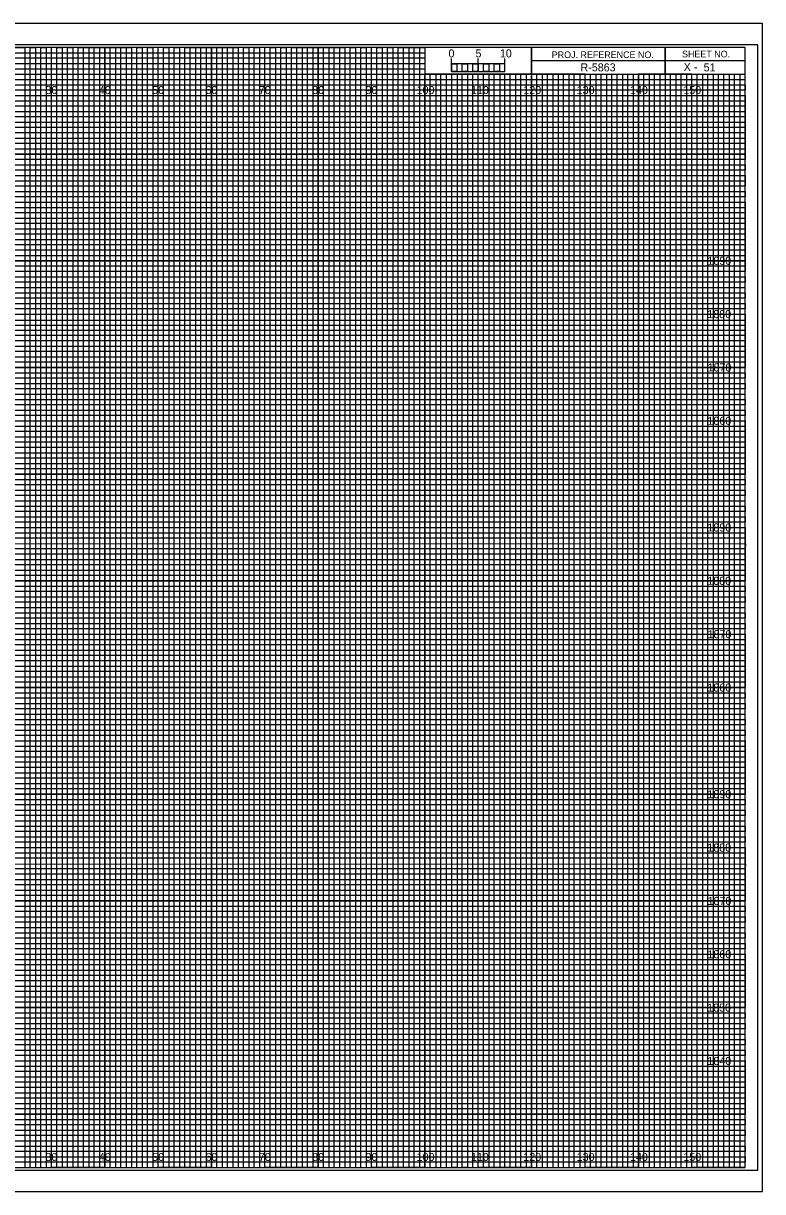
# Model space of a CAD drawing. Extents: x -13 to 323, y 216 to 434.
# Drawn here: x 184.7 to 323.3, y 215.5 to 434.5 of the extents above; entities that cross this region are included whole.
import ezdxf

# ---------------------------------------------------------------- set-up
doc = ezdxf.new("R2010")
doc.units = 0
for name, color, linetype in [('Prop XS Bar Scale Labels', 7, 'Continuous'), ('Prop XS Elevation Labels', 7, 'Continuous'), ('Prop XS Offset Labels', 7, 'Continuous'), ('Prop XS Project Number', 7, 'Continuous'), ('Prop XS Sheet Number', 7, 'Continuous'), ('Sheet Cross Section CELL', 7, 'Continuous'), ('Sheet Cross Section Grid Major CELL', 7, 'Continuous'), ('Sheet Cross Section Grid Middle CELL', 7, 'Continuous'), ('Sheet Cross Section Grid Minor 1 CELL', 7, 'Continuous'), ('Sheet Cross Section Grid Minor 2 CELL', 7, 'Continuous'), ('Sheet Cross Section Scale CELL', 7, 'Continuous'), ('Sheet Cutting Line CELL', 7, 'Continuous'), ('Sheet DOT Grid CELL', 7, 'Continuous'), ('Sheet Plot Border Inside CELL', 7, 'Continuous'), ('Sheet Plot Border Outside CELL', 7, 'Continuous')]:
    doc.layers.add(name, color=color, linetype=linetype)

msp = doc.modelspace()

# ---------------------------------------------------------------- linework, layer by layer
at = {"layer": 'Sheet Cross Section CELL'}
for p, q in [((305, 430), (305, 425)), ((305, 425), (305, 430)), ((280, 427.5), (280, 425)), ((320, 427.49), (280, 427.49)), ((280, 425), (320, 425))]:
    msp.add_line(p, q, dxfattribs=at)
for points in [[(320, 430), (0, 430), (0, 220), (320, 220)], [(280, 430), (260, 430), (260, 425.03), (280, 425.03)], [(320, 430), (280, 430), (280, 425), (320, 425)]]:
    msp.add_lwpolyline(points, close=True, dxfattribs=at)
at = {"layer": 'Sheet Cross Section Grid Major CELL'}
for p, q in [((190, 430), (180, 430)), ((190, 220), (190, 430)), ((210, 430), (200, 430)), ((200, 430), (200, 220)), ((210, 220), (210, 430)), ((230, 430), (220, 430)), ((220, 430), (220, 220)), ((230, 220), (230, 430)), ((250, 430), (240, 430)), ((240, 430), (240, 220)), ((250, 220), (250, 430)), ((260, 430), (260, 220)), ((270, 220), (270, 425)), ((290, 425), (280, 425)), ((280, 425), (280, 220)), ((290, 220), (290, 425)), ((310, 425), (300, 425)), ((300, 425), (300, 220)), ((310, 220), (310, 425)), ((200, 220), (190, 220)), ((220, 220), (210, 220)), ((240, 220), (230, 220)), ((260, 220), (250, 220)), ((280, 220), (270, 220)), ((300, 220), (290, 220)), ((320, 220), (310, 220)), ((320, 220), (320, 220))]:
    msp.add_line(p, q, dxfattribs=at)
for points in [[(0, 420), (320, 420), (320, 410), (0, 410)], [(0, 400), (320, 400), (320, 390), (0, 390)], [(0, 380), (320, 380), (320, 370), (0, 370)], [(0, 360), (320, 360), (320, 350), (0, 350)], [(0, 340), (320, 340), (320, 330), (0, 330)], [(0, 320), (320, 320), (320, 310), (0, 310)], [(0, 300), (320, 300), (320, 290), (0, 290)], [(0, 280), (320, 280), (320, 270), (0, 270)], [(0, 260), (320, 260), (320, 250), (0, 250)], [(0, 240), (320, 240), (320, 230), (0, 230)]]:
    msp.add_lwpolyline(points, dxfattribs=at)
at = {"layer": 'Sheet Cross Section Grid Middle CELL'}
for points in [[(175, 430), (185, 430), (185, 220), (195, 220), (195, 430), (205, 430), (205, 220), (215, 220), (215, 430), (225, 430), (225, 220), (235, 220), (235, 430), (245, 430), (245, 220), (255, 220), (255, 430), (259.93, 430), (260, 430), (260, 425), (264.99, 425), (264.99, 220), (275, 220), (275, 425), (285, 425), (285, 220), (295, 220), (295, 425), (305, 425), (305, 220), (315, 220), (315, 425)], [(0, 425), (275, 425)], [(0, 405), (320, 405), (320, 415), (0, 415)], [(0, 385), (320, 385), (320, 395), (0, 395)], [(0, 365), (320, 365), (320, 375), (0, 375)], [(0, 345), (320, 345), (320, 355), (0, 355)], [(0, 325), (320, 325), (320, 335), (0, 335)], [(0, 305), (320, 305), (320, 315), (0, 315)], [(0, 285), (320, 285), (320, 295), (0, 295)], [(0, 265), (320, 265), (320, 275), (0, 275)], [(0, 245), (320, 245), (320, 255), (0, 255)], [(0, 225), (320, 225), (320, 235), (0, 235)]]:
    msp.add_lwpolyline(points, dxfattribs=at)
at = {"layer": 'Sheet Cross Section Grid Minor 1 CELL'}
for p, q in [((0, 429), (260, 429)), ((260, 427.98), (0, 427.98)), ((260, 429), (260, 427.98)), ((0, 427), (260, 427)), ((260, 425.89), (0, 425.89)), ((260, 427), (260, 425.89)), ((0, 424), (320, 424))]:
    msp.add_line(p, q, dxfattribs=at)
for points in [[(0, 423), (270, 423), (320, 423), (320, 422), (0, 422)], [(0, 421), (320, 421), (320, 419), (0, 419)], [(0, 418), (320, 418), (320, 417), (0, 416.98)], [(0, 416), (320, 416), (320, 414), (0, 414)], [(0, 413), (320, 413), (320, 412), (0, 412)], [(0, 411), (320, 411), (320, 409), (0, 409)], [(0, 408), (320, 408), (320, 407), (0, 407)], [(0, 406), (320, 406), (320, 404), (0, 404)], [(0, 403), (320, 403), (320, 402), (0, 402)], [(0, 401), (320, 401), (320, 399), (0, 399)], [(0, 398), (320, 398), (320, 397), (0, 397)], [(0, 396), (320, 396), (320, 393.95), (320, 393), (320, 392), (0, 392)], [(0, 394), (320, 394), (320, 393), (0, 393)], [(0, 391), (320, 391), (320, 389), (0, 389.03)], [(0, 389.03), (320, 389), (320, 388), (0, 388)], [(0, 387), (320, 387), (320, 386), (0, 386)], [(0, 384), (320, 384), (320, 383), (0, 383)], [(0, 382), (320, 382), (320, 381), (0, 381)], [(-0.07, 378.89), (320, 378.89), (320, 377.88), (-0.07, 377.88)], [(0, 377), (320, 377), (320, 376), (0, 376)], [(0, 374), (320, 374), (320, 373), (0, 373)], [(0, 372), (320, 372), (320, 371), (0, 371)], [(0, 369), (320, 369), (320, 368), (0, 368)], [(0, 367), (320, 367), (320, 366), (0, 366)], [(0, 364), (320, 364), (320, 363), (0, 363)], [(0, 362), (320, 362), (320, 361), (0, 361)], [(0, 359), (320, 359), (319.99, 357.98), (0, 358)], [(0, 357), (320, 357), (320, 356), (0, 356)], [(0, 354), (320, 354), (320, 353), (0, 353)], [(0, 352), (320, 352), (320, 351), (0, 351)], [(0, 349), (320, 349), (320, 348), (0, 348)], [(0, 347), (320, 347), (320, 346), (0, 346)], [(0, 344), (320, 344), (320, 343), (0, 343)], [(0, 342), (320, 342), (320, 341), (0, 341)], [(0, 339), (320, 339), (320, 338), (0, 338)], [(0, 336.99), (320.07, 336.91), (320, 336), (0, 336)], [(0, 334), (320, 334), (320, 333), (0, 333)], [(0, 332), (320, 332), (320, 331), (0, 331)], [(0, 329), (320, 329), (320, 328), (0, 328)], [(0, 327), (320, 327), (320, 326), (0, 326)], [(0, 324), (320, 324), (320, 323), (0, 323)], [(0, 322), (320, 322), (320, 321), (0, 321)], [(0, 319), (320, 319), (320, 318), (0, 318)], [(0, 317), (320, 317), (320, 316), (0, 316)], [(0, 314), (320, 314), (320, 313), (0, 313)], [(0, 312), (320, 312), (320, 311), (0, 311)], [(0, 309), (320, 309), (320, 308), (0, 308)], [(0, 307), (320, 307), (320, 306), (0, 306)], [(0, 304), (320, 304), (320, 303), (0, 303)], [(0, 302), (320, 302), (320, 301), (0, 301)], [(0, 299), (320, 299), (319.99, 297.98), (0, 298)], [(0, 297), (320, 297), (320, 296), (0, 296)], [(0, 294), (320, 294), (320, 293), (0, 293)], [(0, 292), (320, 292), (320, 291), (0, 291)], [(0, 289), (320, 289), (320, 288), (0, 288)], [(0, 287), (320, 287), (320, 286), (0, 286)], [(0, 284), (320, 284), (320, 283), (0, 283)], [(0, 282), (320, 282), (320, 281), (0, 281)], [(0, 279), (320, 279), (320, 278), (0, 278)], [(0, 276.99), (320.07, 276.91), (320, 276), (0, 276)], [(0, 274), (320, 274), (320, 273), (0, 273)], [(0, 272), (320, 272), (320, 271), (0, 271)], [(0, 269), (320, 269), (320, 268), (0, 268)], [(0, 267), (320, 267), (320, 266), (0, 266)], [(0, 264), (320, 264), (320, 263), (0, 263)], [(0, 262), (320, 262), (320, 261), (0, 261)], [(0, 259), (320, 259), (320, 258), (0, 258)], [(0, 257), (320, 257), (320, 256), (0, 256)], [(0, 254), (320, 254), (320, 253), (0, 253)], [(0, 252), (320, 252), (320, 251), (0, 251)], [(0, 249), (320, 249), (320, 248), (0, 248)], [(0, 247), (320, 247), (320, 246), (0, 246)], [(0, 244), (320, 244), (320, 243), (0, 243)], [(0, 242), (320, 242), (320, 241), (0, 241)], [(0, 239), (320, 239), (320, 238), (0, 238)], [(0, 237), (320, 237), (320, 236), (0, 236)], [(0, 234), (320, 234), (320, 233), (0, 233)], [(0, 232), (320, 232), (320, 231), (0, 231)], [(0, 229), (320, 229), (320, 228), (0, 228)], [(0, 227), (320, 227), (320, 226), (0, 226)], [(0, 224), (320, 224), (320, 223), (0, 223)], [(0, 222), (320, 222), (320, 221), (0, 221)]]:
    msp.add_lwpolyline(points, dxfattribs=at)
at = {"layer": 'Sheet Cross Section Grid Minor 2 CELL'}
for p, q in [((267, 425), (266.01, 425)), ((266.01, 425), (266.01, 220)), ((267, 220), (267, 425)), ((269, 425), (268, 425)), ((268, 425), (268, 220)), ((269, 220), (269, 425)), ((266.01, 220), (265, 220)), ((268, 220), (267, 220))]:
    msp.add_line(p, q, dxfattribs=at)
for points in [[(185, 220), (186, 220), (186, 430), (187, 430), (187, 220)], [(187, 220), (188, 220), (188, 430), (189, 430), (189, 220)], [(190, 220), (191, 220), (191, 430), (192, 430), (192, 220)], [(192, 220), (193, 220), (193, 430), (194, 430), (194, 220)], [(195, 220), (196, 220), (196, 430), (197, 430), (197, 220)], [(197, 220), (198, 220), (198, 430), (199, 430), (199, 220)], [(200, 220), (201, 220), (201, 430), (202, 430), (202, 220)], [(202, 220), (203, 220), (203, 430), (204, 430), (204, 220)], [(205, 220), (206, 220), (206, 430), (207, 430), (207, 220)], [(207, 220), (208, 220), (208, 430), (209, 430), (209, 220)], [(210, 220), (211, 220), (211, 430), (212, 430), (212, 220)], [(212, 220), (213, 220), (213, 430), (214, 430), (214, 220)], [(215, 220), (216, 220), (216, 430), (217, 430), (217, 220)], [(217, 220), (218, 220), (218, 430), (219, 430), (219, 220)], [(220, 220), (221, 220), (221, 430), (222, 430), (222, 220)], [(222, 220), (223, 220), (223, 430), (224, 430), (224, 220)], [(225, 220), (226, 220), (226, 430), (227, 430), (227, 220)], [(227, 220), (228, 220), (228, 430), (229, 430), (229, 220)], [(230, 220), (231, 220), (231, 430), (232, 430), (232, 220)], [(232, 220), (233, 220), (233, 430), (234, 430), (234, 220)], [(235, 220), (236, 220), (236, 430), (237, 430), (237, 220)], [(237, 220), (238, 220), (238, 430), (239, 430), (239, 220)], [(240, 220), (241, 220), (241, 430), (242, 430), (242, 220)], [(242, 220), (243, 220), (243, 430), (244, 430), (244, 220)], [(245, 220), (246, 220), (246, 430), (247, 430), (247, 220)], [(247, 220), (248, 220), (248, 430), (249, 430), (249, 220)], [(250, 220), (251, 220), (251, 430), (252, 430), (252, 220)], [(252, 220), (253, 220), (253, 430), (254, 430), (254, 220)], [(255, 220), (256, 220), (256, 430), (257, 430), (257, 220)], [(257, 220), (258, 220), (258, 430), (259, 430), (259, 220)], [(260, 220), (261, 220), (261, 425), (262.02, 425), (262.02, 220)], [(262, 220), (263, 220), (263, 425), (263.99, 425), (263.99, 220)], [(270, 220), (270.98, 220), (270.98, 425), (272, 425), (272, 220)], [(272, 220), (273, 220), (273, 425), (274.05, 425), (274.05, 220)], [(275, 220), (276, 220), (276, 425), (277, 425), (277, 220)], [(277, 220), (278, 220), (278, 425), (279, 425), (279, 220)], [(280, 220), (281, 220), (281, 425), (282, 425), (282, 220)], [(282, 220), (283, 220), (283, 425), (284, 425), (284, 220)], [(285, 220), (286, 220), (286, 425), (287, 425), (287, 220)], [(287, 220), (288, 220), (288, 425), (289, 425), (289, 220)], [(290, 220), (291, 220), (291, 425), (292, 425), (292, 220)], [(292, 220), (293, 220), (293, 425), (294, 425), (294, 220)], [(295, 220), (296, 220), (296, 425), (297, 425), (297, 220)], [(297, 220), (298, 220), (298, 425), (299, 425), (299, 220)], [(300, 220), (301, 220), (301, 425), (302, 425), (302, 220)], [(302, 220), (303, 220), (303, 425), (304, 425), (304, 220)], [(305, 220), (306, 220), (306, 425), (307, 425), (307, 220)], [(307, 220), (308, 220), (308, 425), (309, 425), (309, 220)], [(310, 220), (311, 220), (311, 425), (312, 425), (312, 220)], [(312, 220), (313, 220), (313, 425), (314, 425), (314, 220)], [(315, 220), (316, 220), (316, 425), (317, 425), (317, 220)], [(317, 220), (318, 220), (318, 425), (319, 425), (319, 220)]]:
    msp.add_lwpolyline(points, dxfattribs=at)
at = {"layer": 'Sheet Cross Section Scale CELL'}
for p, q in [((265, 425.49), (265, 427.9)), ((265, 426.9), (265, 427.9)), ((270, 425.49), (270, 427.9)), ((275, 425.49), (275, 427.9)), ((275, 426.9), (275, 427.9))]:
    msp.add_line(p, q, dxfattribs=at)
for points in [[(275, 426.9), (265, 426.9), (265, 425.49), (275, 425.49)], [(265, 426.9), (266, 426.9), (266, 425.49), (265, 425.49)], [(267, 426.9), (268, 426.9), (268, 425.49), (267, 425.49)], [(269, 426.9), (270, 426.9), (270, 425.49), (269, 425.49)], [(271, 426.9), (272, 426.9), (272, 425.49), (271, 425.49)], [(273, 426.9), (274, 426.9), (274, 425.49), (273, 425.49)]]:
    msp.add_lwpolyline(points, close=True, dxfattribs=at)
at = {"layer": 'Sheet Cutting Line CELL'}
for p, q in [((323.3, 434.5), (-13.4, 434.5)), ((-13.4, 215.5), (323.3, 215.5))]:
    msp.add_line(p, q, dxfattribs=at)
at = {"layer": 'Sheet DOT Grid CELL'}
for p, q in [((190, 220), (190, 430)), ((200, 220), (200, 430)), ((210, 220), (210, 430)), ((220, 220), (220, 430)), ((230, 220), (230, 430)), ((240, 220), (240, 430)), ((250, 220), (250, 430)), ((260, 220), (260, 424.69)), ((270, 220), (270, 424.69)), ((280, 220), (280, 424.69)), ((290, 220), (290, 424.69)), ((300, 220), (300, 424.69)), ((310, 220), (310, 424.69)), ((0, 420), (320, 420)), ((0, 410), (320, 410)), ((0, 400), (320, 400)), ((0, 390), (320, 390)), ((0, 380), (320, 380)), ((0, 370), (320, 370)), ((0, 360), (320, 360)), ((0, 350), (320, 350)), ((0, 340), (320, 340)), ((0, 330), (320, 330)), ((0, 320), (320, 320)), ((0, 310), (320, 310)), ((0, 300), (320, 300)), ((0, 290), (320, 290)), ((0, 280), (320, 280)), ((0, 270), (320, 270)), ((0, 260), (320, 260)), ((0, 250), (320, 250)), ((0, 240), (320, 240)), ((0, 230), (320, 230))]:
    msp.add_line(p, q, dxfattribs=at)
at = {"layer": 'Sheet Plot Border Inside CELL'}
msp.add_lwpolyline([(-10.8, 219.5), (322.4, 219.5), (322.4, 430.5), (-10.8, 430.5)], close=True, dxfattribs=at)
at = {"layer": 'Sheet Plot Border Outside CELL'}
msp.add_lwpolyline([(-13.4, 215.5), (323.3, 215.5), (323.3, 434.5), (-13.4, 434.5)], close=True, dxfattribs=at)

# ---------------------------------------------------------------- texts
at = {"layer": 'Prop XS Bar Scale Labels'}
for s, p in [('5', (269.47, 428.12)), ('10', (274.04, 428.12))]:
    msp.add_text(s, height=1.5, dxfattribs=at).set_placement(p)
at = {"layer": 'Prop XS Elevation Labels'}
for s, p in [('1890', (312.95, 389.25)), ('1880', (312.92, 379.25)), ('1870', (312.98, 369.25)), ('1860', (312.95, 359.25)), ('1890', (312.95, 339.25)), ('1880', (312.92, 329.25)), ('1870', (312.98, 319.25)), ('1860', (312.95, 309.25)), ('1890', (312.95, 289.25)), ('1880', (312.92, 279.25)), ('1870', (312.98, 269.25)), ('1860', (312.95, 259.25)), ('1850', (312.9, 249.25)), ('1840', (312.95, 239.25))]:
    msp.add_text(s, height=1.5, dxfattribs=at).set_placement(p)
at = {"layer": 'Prop XS Offset Labels'}
for s, p in [('30', (188.86, 421.25)), ('40', (198.86, 421.25)), ('50', (208.86, 421.25)), ('60', (218.86, 421.25)), ('70', (228.86, 421.25)), ('80', (238.86, 421.25)), ('90', (248.86, 421.25)), ('100', (258.44, 421.25)), ('110', (268.62, 421.25)), ('120', (278.44, 421.25)), ('130', (288.44, 421.25)), ('140', (298.44, 421.25)), ('150', (308.44, 421.25)), ('30', (188.86, 221.25)), ('40', (198.86, 221.25)), ('50', (208.86, 221.25)), ('60', (218.86, 221.25)), ('70', (228.86, 221.25)), ('80', (238.86, 221.25)), ('90', (248.86, 221.25)), ('100', (258.44, 221.25)), ('110', (268.62, 221.25)), ('120', (278.44, 221.25)), ('130', (288.44, 221.25)), ('140', (298.44, 221.25)), ('150', (308.44, 221.25))]:
    msp.add_text(s, height=1.5, dxfattribs=at).set_placement(p)
at = {"layer": 'Prop XS Project Number'}
msp.add_text('R-5863', height=1.5, dxfattribs=at).set_placement((289.16, 425.5))
at = {"layer": 'Prop XS Sheet Number'}
msp.add_text('51', height=1.5, dxfattribs=at).set_placement((312.25, 425.5))
at = {"layer": 'Sheet Cross Section CELL'}
for s, height, p in [('PROJ. REFERENCE NO.', 1.25, (283.77, 427.99)), ('SHEET NO.', 1.25, (308.19, 428.12)), ('X -    ', 1.5, (308.5, 425.58))]:
    msp.add_text(s, height=height, dxfattribs=at).set_placement(p)
at = {"layer": 'Sheet Cross Section Scale CELL'}
msp.add_text('0', height=1.5, dxfattribs=at).set_placement((264.41, 428.12))

doc.saveas('drawing.dxf')
